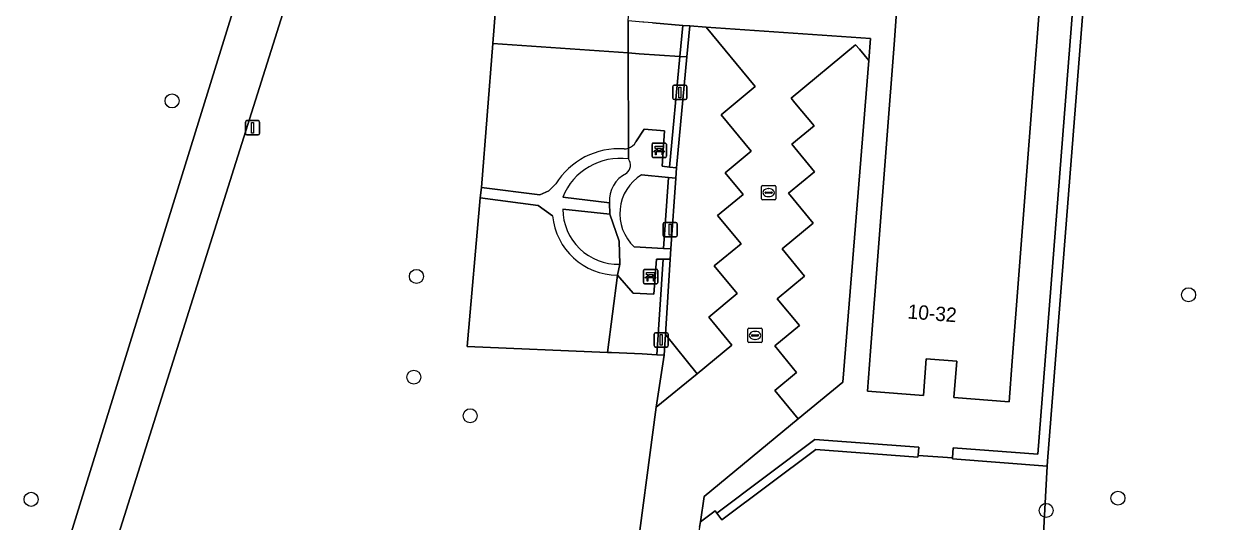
# Model space of a CAD drawing. Extents: x 161402 to 161933, y 381647 to 382315.
# Drawn here: x 161588.1 to 161672, y 381714.1 to 381748.8 of the extents above; entities that cross this region are included whole.
import ezdxf

# ---------------------------------------------------------------- set-up
doc = ezdxf.new("R2010")
doc.units = 0
for name, color, linetype in [('IMGEO_Bank', 7, 'Continuous'), ('IMGEO_Boom', 7, 'Continuous'), ('IMGEO_Groenvoorziening', 7, 'Continuous'), ('IMGEO_Haag', 7, 'Continuous'), ('IMGEO_Hek', 7, 'Continuous'), ('IMGEO_Kolk', 7, 'Continuous'), ('IMGEO_Lichtmast', 7, 'Continuous'), ('IMGEO_Pand', 7, 'Continuous'), ('IMGEO_Pand_nummerreeks', 7, 'Continuous'), ('IMGEO_Parkeervlak_open', 7, 'Continuous'), ('IMGEO_Rijbaan_lokaal_open', 7, 'Continuous'), ('IMGEO_Voetpad_gesloten', 7, 'Continuous'), ('IMGEO_Voetpad_open', 7, 'Continuous')]:
    doc.layers.add(name, color=color, linetype=linetype)

msp = doc.modelspace()

# ---------------------------------------------------------------- linework, layer by layer
at = {"layer": 'IMGEO_Bank'}
for p, q in [((161631.866, 381739.608), (161631.866, 381740.449)), ((161631.866, 381740.449), (161631.866, 381739.608)), ((161631.941, 381740.533), (161632.782, 381740.533)), ((161632.782, 381740.533), (161631.941, 381740.533)), ((161632.563, 381739.931), (161632.17, 381739.931)), ((161632.175, 381740.039), (161632.175, 381740.145)), ((161632.219, 381740.145), (161632.219, 381740.039)), ((161632.507, 381740.151), (161632.225, 381740.151)), ((161632.225, 381740.033), (161632.507, 381740.033)), ((161632.513, 381740.039), (161632.513, 381740.145)), ((161632.557, 381740.145), (161632.557, 381740.039)), ((161632.866, 381740.458), (161632.866, 381739.617)), ((161632.866, 381739.617), (161632.866, 381740.458)), ((161632.791, 381739.533), (161631.95, 381739.533)), ((161631.95, 381739.533), (161632.791, 381739.533)), ((161631.268, 381730.81), (161631.268, 381731.651)), ((161631.268, 381731.651), (161631.268, 381730.81)), ((161631.343, 381731.735), (161632.184, 381731.735)), ((161632.184, 381731.735), (161631.343, 381731.735)), ((161632.268, 381731.66), (161632.268, 381730.819)), ((161632.268, 381730.819), (161632.268, 381731.66)), ((161632.193, 381730.735), (161631.352, 381730.735)), ((161631.352, 381730.735), (161632.193, 381730.735)), ((161631.965, 381731.133), (161631.572, 381731.133)), ((161631.577, 381731.241), (161631.577, 381731.347)), ((161631.621, 381731.347), (161631.621, 381731.241)), ((161631.909, 381731.353), (161631.627, 381731.353)), ((161631.627, 381731.235), (161631.909, 381731.235)), ((161631.915, 381731.241), (161631.915, 381731.347)), ((161631.959, 381731.347), (161631.959, 381731.241))]:
    msp.add_line(p, q, dxfattribs=at)
for points in [[(161632.113, 381739.931), (161631.971, 381739.931), (161632.083, 381740.033), (161632.169, 381740.033)], [(161632.169, 381740.151), (161632.083, 381740.151), (161632.083, 381740.312), (161632.646, 381740.312), (161632.646, 381740.151), (161632.563, 381740.151)], [(161632.163, 381739.924), (161632.163, 381739.717), (161632.12, 381739.717), (161632.12, 381739.924)], [(161632.563, 381740.033), (161632.646, 381740.033), (161632.758, 381739.931), (161632.619, 381739.931)], [(161632.613, 381739.924), (161632.613, 381739.717), (161632.569, 381739.717), (161632.569, 381739.924)], [(161631.515, 381731.133), (161631.373, 381731.133), (161631.485, 381731.235), (161631.571, 381731.235)], [(161631.571, 381731.353), (161631.485, 381731.353), (161631.485, 381731.514), (161632.048, 381731.514), (161632.048, 381731.353), (161631.965, 381731.353)], [(161631.565, 381731.126), (161631.565, 381730.919), (161631.522, 381730.919), (161631.522, 381731.126)], [(161631.965, 381731.235), (161632.048, 381731.235), (161632.16, 381731.133), (161632.021, 381731.133)], [(161632.015, 381731.126), (161632.015, 381730.919), (161631.971, 381730.919), (161631.971, 381731.126)]]:
    msp.add_lwpolyline(points, dxfattribs=at)
for centre, radius, start, end in [((161631.944, 381740.455), 0.0779, 92.4484, 184.28452), ((161631.944, 381740.455), 0.0779, 92.4484, 184.28452), ((161632.113, 381739.924), 0.00671, 2.89567, 87.10433), ((161632.17, 381739.924), 0.00671, 92.89567, 177.10433), ((161632.168, 381740.144), 0.00671, 2.89567, 87.10433), ((161632.168, 381740.04), 0.00671, 272.89567, 357.10433), ((161632.225, 381740.144), 0.00671, 92.89567, 177.10433), ((161632.225, 381740.04), 0.00671, 182.89567, 267.10433), ((161632.507, 381740.144), 0.00671, 2.89567, 87.10433), ((161632.507, 381740.04), 0.00671, 272.89567, 357.10433), ((161632.564, 381740.144), 0.00671, 92.89567, 177.10433), ((161632.564, 381740.04), 0.00671, 182.89567, 267.10433), ((161632.562, 381739.924), 0.00671, 2.89567, 87.10433), ((161632.619, 381739.924), 0.00671, 92.89567, 177.10433), ((161632.788, 381740.455), 0.0779, 2.4484, 94.28452), ((161632.788, 381740.455), 0.0779, 2.4484, 94.28452), ((161631.944, 381739.611), 0.0779, 182.4484, 274.28452), ((161631.944, 381739.611), 0.0779, 182.4484, 274.28452), ((161632.788, 381739.611), 0.0779, 272.4484, 4.28452), ((161632.788, 381739.611), 0.0779, 272.4484, 4.28452), ((161631.346, 381731.657), 0.0779, 92.4484, 184.28452), ((161631.346, 381731.657), 0.0779, 92.4484, 184.28452), ((161632.19, 381731.657), 0.0779, 2.4484, 94.28452), ((161632.19, 381731.657), 0.0779, 2.4484, 94.28452), ((161631.346, 381730.813), 0.0779, 182.4484, 274.28452), ((161631.346, 381730.813), 0.0779, 182.4484, 274.28452), ((161631.515, 381731.126), 0.00671, 2.89567, 87.10433), ((161631.572, 381731.126), 0.00671, 92.89567, 177.10433), ((161631.57, 381731.346), 0.00671, 2.89567, 87.10433), ((161631.57, 381731.242), 0.00671, 272.89567, 357.10433), ((161631.627, 381731.346), 0.00671, 92.89567, 177.10433), ((161631.627, 381731.242), 0.00671, 182.89567, 267.10433), ((161631.909, 381731.346), 0.00671, 2.89567, 87.10433), ((161631.909, 381731.242), 0.00671, 272.89567, 357.10433), ((161631.966, 381731.346), 0.00671, 92.89567, 177.10433), ((161631.966, 381731.242), 0.00671, 182.89567, 267.10433), ((161631.964, 381731.126), 0.00671, 2.89567, 87.10433), ((161632.021, 381731.126), 0.00671, 92.89567, 177.10433), ((161632.19, 381730.813), 0.0779, 272.4484, 4.28452), ((161632.19, 381730.813), 0.0779, 272.4484, 4.28452)]:
    msp.add_arc(centre, radius, start, end, dxfattribs=at)
at = {"layer": 'IMGEO_Boom'}
for centre in [(161598.377, 381743.475), (161615.428, 381731.244), (161669.305, 381729.962), (161615.249, 381724.221), (161619.18, 381721.53), (161588.542, 381715.703), (161664.377, 381715.786), (161659.366, 381714.93)]:
    msp.add_circle(centre, 0.489, dxfattribs=at)
at = {"layer": 'IMGEO_Groenvoorziening'}
for points in [[(161588.768, 381710.585), (161590.391, 381710.295), (161602.713, 381750), (161618.166, 381798.995)], [(161663.284, 381767.646), (161664.69, 381767.597), (161668.364, 381767.469), (161668.237, 381759.952), (161664.228, 381760.017), (161662.713, 381760.042), (161661.941, 381749.945), (161659.461, 381718.372), (161659.442, 381718.025), (161658.506, 381700.881), (161673.928, 381698.758), (161680.023, 381713.112), (161687.661, 381714.218), (161685.628, 381737.233), (161688.746, 381737.387), (161691.747, 381737.535), (161690.482, 381750)], [(161629.207, 381767.096), (161621.922, 381762.295), (161620.756, 381747.469), (161630.207, 381746.819), (161630.203, 381749.059), (161630.276, 381750), (161630.835, 381757.212), (161630.915, 381761.438), (161639.403, 381761.221), (161639.486, 381762.057), (161638.004, 381762.183), (161634.216, 381762.507)], [(161606.251, 381750), (161593.549, 381709.799), (161595.559, 381709.521), (161607.044, 381707.963), (161607.264, 381709.577), (161610.846, 381709.061), (161610.603, 381707.437), (161625.819, 381705.367), (161626.558, 381710.972), (161626.855, 381710.928), (161630.603, 381710.376), (161632.151, 381722.118), (161632.708, 381725.764), (161632.208, 381725.787), (161631.169, 381725.836), (161629.04, 381725.928), (161628.771, 381725.94), (161618.968, 381726.363), (161619.878, 381736.709), (161619.968, 381737.446), (161620.756, 381747.469), (161621.922, 381762.295)], [(161630.218, 381740.179), (161630.207, 381746.819), (161620.756, 381747.469), (161619.968, 381737.446), (161624.039, 381736.932), (161624.661, 381737.206), (161625.145, 381737.685)], [(161630.731, 381740.617), (161631.321, 381741.506), (161632.748, 381741.385), (161632.564, 381738.922), (161633.077, 381738.869), (161633.805, 381746.571), (161630.967, 381746.766), (161630.207, 381746.819), (161630.218, 381740.179)], [(161630.617, 381733.304), (161632.678, 381733.185), (161633.026, 381738.144), (161631.134, 381738.322)], [(161624.931, 381735.468), (161623.917, 381736.185), (161619.878, 381736.709), (161618.968, 381726.363), (161628.771, 381725.94), (161629.458, 381731.326)], [(161625.635, 381736.767), (161628.902, 381736.38)], [(161629.611, 381732.088), (161629.564, 381733.696), (161628.935, 381735.57), (161625.64, 381735.928)]]:
    msp.add_lwpolyline(points, dxfattribs=at)
for points in [[(161662.713, 381760.042), (161662.409, 381760.047), (161662.012, 381760.054), (161661.227, 381750), (161658.796, 381718.845), (161652.885, 381719.282), (161652.831, 381718.594), (161652.825, 381718.515), (161659.442, 381718.025), (161659.461, 381718.372), (161661.941, 381749.945)], [(161634.01, 381748.744), (161631.893, 381748.919), (161631.295, 381748.969), (161631.218, 381748.975), (161630.203, 381749.059), (161630.207, 381746.819), (161630.967, 381746.766), (161633.805, 381746.571)], [(161634.304, 381746.537), (161634.509, 381748.703), (161634.01, 381748.744), (161633.805, 381746.571)], [(161633.575, 381738.817), (161634.304, 381746.537), (161633.805, 381746.571), (161633.077, 381738.869)], [(161633.177, 381733.156), (161633.524, 381738.097), (161633.026, 381738.144), (161632.678, 381733.185)], [(161629.04, 381725.928), (161631.169, 381725.836), (161632.208, 381725.787), (161632.641, 381732.452), (161632.191, 381732.454), (161631.991, 381729.995), (161630.552, 381730.063), (161629.458, 381731.326), (161628.771, 381725.94)], [(161633.142, 381732.449), (161632.641, 381732.452), (161632.208, 381725.787), (161632.708, 381725.764), (161632.8, 381727.185)], [(161643.225, 381719.866), (161636.381, 381714.742), (161636.738, 381714.264), (161643.3, 381719.172), (161650.424, 381718.643), (161650.433, 381718.759), (161650.477, 381719.329)], [(161659.442, 381718.025), (161652.825, 381718.515), (161652.831, 381718.594), (161650.433, 381718.759), (161650.424, 381718.643), (161643.3, 381719.172), (161636.738, 381714.264), (161636.381, 381714.742), (161636.265, 381714.897), (161635.242, 381714.132), (161635.188, 381713.771), (161633.775, 381704.284), (161633.894, 381704.268), (161658.506, 381700.881)]]:
    msp.add_lwpolyline(points, close=True, dxfattribs=at)
for centre, radius, start, end in [((161629.553, 381734.955), 5.185, 86.02348, 148.23538), ((161629.912, 381741.073), 0.945, 270.07116, 288.9144), ((161629.92, 381741.047), 0.918, 288.93213, 332.04935), ((161629.644, 381735.151), 4.322, 82.35266, 158.04824), ((161629.626, 381739.001), 0.735, 308.0568, 36.20596), ((161631.014, 381736.523), 2.117, 116.20928, 183.87279), ((161632.793, 381735.615), 3.174, 121.49947, 226.73578), ((161629.508, 381735.954), 3.868, 180.39129, 271.53037), ((161629.486, 381735.902), 4.576, 185.4366, 269.64919)]:
    msp.add_arc(centre, radius, start, end, dxfattribs=at)
at = {"layer": 'IMGEO_Haag'}
for points in [[(161662.713, 381760.042), (161662.409, 381760.047), (161662.012, 381760.054), (161661.227, 381750), (161658.796, 381718.845), (161652.885, 381719.282), (161652.831, 381718.594), (161652.825, 381718.515), (161659.442, 381718.025), (161659.461, 381718.372), (161661.941, 381749.945)], [(161634.509, 381748.703), (161634.01, 381748.744), (161633.805, 381746.571), (161634.304, 381746.537)], [(161634.304, 381746.537), (161633.805, 381746.571), (161633.077, 381738.869), (161633.575, 381738.817)], [(161633.177, 381733.156), (161633.524, 381738.097), (161633.026, 381738.144), (161632.678, 381733.185)], [(161633.142, 381732.449), (161632.641, 381732.452), (161632.208, 381725.787), (161632.708, 381725.764), (161632.8, 381727.185)], [(161643.225, 381719.866), (161636.381, 381714.742), (161636.738, 381714.264), (161643.3, 381719.172), (161650.424, 381718.643), (161650.433, 381718.759), (161650.477, 381719.329)]]:
    msp.add_lwpolyline(points, close=True, dxfattribs=at)
at = {"layer": 'IMGEO_Hek'}
for points in [[(161630.207, 381746.819), (161620.756, 381747.469)], [(161630.967, 381746.766), (161630.207, 381746.819)], [(161633.805, 381746.571), (161630.967, 381746.766)], [(161634.304, 381746.537), (161633.805, 381746.571)]]:
    msp.add_lwpolyline(points, dxfattribs=at)
at = {"layer": 'IMGEO_Kolk'}
for p, q in [((161639.503, 381736.655), (161639.503, 381737.507)), ((161639.578, 381737.581), (161640.43, 381737.581)), ((161640.504, 381737.507), (161640.504, 381736.655)), ((161640.43, 381736.581), (161639.578, 381736.581)), ((161639.762, 381737.075), (161639.762, 381737.087)), ((161640.2, 381737.038), (161639.802, 381737.038)), ((161639.805, 381737.124), (161640.203, 381737.124)), ((161640.014, 381736.801), (161639.989, 381736.801)), ((161639.991, 381737.361), (161640.016, 381737.361)), ((161640.246, 381737.087), (161640.246, 381737.075)), ((161638.556, 381726.702), (161638.556, 381727.554)), ((161638.631, 381727.628), (161639.483, 381727.628)), ((161639.044, 381727.408), (161639.069, 381727.408)), ((161639.557, 381727.554), (161639.557, 381726.702)), ((161639.483, 381726.628), (161638.631, 381726.628)), ((161638.815, 381727.122), (161638.815, 381727.134)), ((161639.253, 381727.085), (161638.855, 381727.085)), ((161638.858, 381727.171), (161639.256, 381727.171)), ((161639.067, 381726.848), (161639.042, 381726.848)), ((161639.299, 381727.134), (161639.299, 381727.122))]:
    msp.add_line(p, q, dxfattribs=at)
for points in [[(161639.503, 381736.655), (161639.503, 381737.507)], [(161639.578, 381737.581), (161640.43, 381737.581)], [(161640.504, 381737.507), (161640.504, 381736.655)], [(161640.43, 381736.581), (161639.578, 381736.581)], [(161638.556, 381726.702), (161638.556, 381727.554)], [(161638.631, 381727.628), (161639.483, 381727.628)], [(161639.557, 381727.554), (161639.557, 381726.702)], [(161639.483, 381726.628), (161638.631, 381726.628)]]:
    msp.add_lwpolyline(points, dxfattribs=at)
for centre, radius, start, end in [((161639.58, 381737.505), 0.0765, 91.55205, 178.44795), ((161639.58, 381737.505), 0.0765, 91.55205, 178.44795), ((161640.428, 381737.505), 0.0765, 1.55205, 88.44795), ((161640.428, 381737.505), 0.0765, 1.55205, 88.44795), ((161639.58, 381736.657), 0.0765, 181.55205, 268.44795), ((161639.58, 381736.657), 0.0765, 181.55205, 268.44795), ((161639.802, 381737.084), 0.0403, 85.87752, 175.75265), ((161639.799, 381737.074), 0.0366, 178.93798, 274.71019), ((161640.203, 381737.081), 0.043, 264.86636, 352.45326), ((161640.207, 381737.086), 0.0386, 1.73085, 96.63898), ((161640.428, 381736.657), 0.0765, 271.55205, 358.44795), ((161640.428, 381736.657), 0.0765, 271.55205, 358.44795), ((161638.633, 381727.552), 0.0765, 91.55205, 178.44795), ((161638.633, 381727.552), 0.0765, 91.55205, 178.44795), ((161639.481, 381727.552), 0.0765, 1.55205, 88.44795), ((161639.481, 381727.552), 0.0765, 1.55205, 88.44795), ((161638.633, 381726.704), 0.0765, 181.55205, 268.44795), ((161638.633, 381726.704), 0.0765, 181.55205, 268.44795), ((161638.855, 381727.131), 0.0403, 85.87752, 175.75265), ((161638.852, 381727.121), 0.0366, 178.93798, 274.71019), ((161639.256, 381727.128), 0.043, 264.86636, 352.45326), ((161639.26, 381727.133), 0.0386, 1.73085, 96.63898), ((161639.481, 381726.704), 0.0765, 271.55205, 358.44795), ((161639.481, 381726.704), 0.0765, 271.55205, 358.44795)]:
    msp.add_arc(centre, radius, start, end, dxfattribs=at)
for centre, major_axis, ratio, start_param, end_param in [((161639.99, 381737.081), (-0.387, 0.002), 0.722429, 4.712389, 7.853982), ((161640.015, 381737.081), (-0.39, 0.002), 0.717154, 1.570796, 4.712389), ((161639.043, 381727.128), (-0.387, 0.002), 0.722429, 4.712389, 7.853982), ((161639.068, 381727.128), (-0.39, 0.002), 0.717154, 1.570796, 4.712389)]:
    msp.add_ellipse(centre, major_axis=major_axis, ratio=ratio, start_param=start_param, end_param=end_param, dxfattribs=at)
at = {"layer": 'IMGEO_Lichtmast'}
for p, q in [((161633.316, 381743.669), (161633.316, 381744.469)), ((161633.316, 381744.469), (161633.316, 381743.669)), ((161633.416, 381744.569), (161634.206, 381744.569)), ((161634.206, 381744.569), (161633.416, 381744.569)), ((161634.306, 381744.469), (161634.306, 381743.669)), ((161634.306, 381743.669), (161634.306, 381744.469)), ((161634.206, 381743.569), (161633.416, 381743.569)), ((161633.416, 381743.569), (161634.206, 381743.569)), ((161603.501, 381741.203), (161603.501, 381742.003)), ((161603.501, 381742.003), (161603.501, 381741.203)), ((161603.601, 381742.103), (161604.391, 381742.103)), ((161604.391, 381742.103), (161603.601, 381742.103)), ((161604.491, 381742.003), (161604.491, 381741.203)), ((161604.491, 381741.203), (161604.491, 381742.003)), ((161604.391, 381741.103), (161603.601, 381741.103)), ((161603.601, 381741.103), (161604.391, 381741.103)), ((161632.637, 381734.099), (161632.637, 381734.899)), ((161632.637, 381734.899), (161632.637, 381734.099)), ((161632.737, 381734.999), (161633.527, 381734.999)), ((161633.527, 381734.999), (161632.737, 381734.999)), ((161633.627, 381734.899), (161633.627, 381734.099)), ((161633.627, 381734.099), (161633.627, 381734.899)), ((161633.527, 381733.999), (161632.737, 381733.999)), ((161632.737, 381733.999), (161633.527, 381733.999)), ((161632.006, 381726.416), (161632.006, 381727.216)), ((161632.006, 381727.216), (161632.006, 381726.416)), ((161632.106, 381727.316), (161632.896, 381727.316)), ((161632.896, 381727.316), (161632.106, 381727.316)), ((161632.996, 381727.216), (161632.996, 381726.416)), ((161632.996, 381726.416), (161632.996, 381727.216)), ((161632.896, 381726.316), (161632.106, 381726.316)), ((161632.106, 381726.316), (161632.896, 381726.316))]:
    msp.add_line(p, q, dxfattribs=at)
for points in [[(161633.736, 381744.444), (161633.886, 381744.444), (161633.886, 381743.694), (161633.736, 381743.694), (161633.736, 381744.444)], [(161603.921, 381741.978), (161604.071, 381741.978), (161604.071, 381741.228), (161603.921, 381741.228), (161603.921, 381741.978)], [(161633.057, 381734.874), (161633.207, 381734.874), (161633.207, 381734.124), (161633.057, 381734.124), (161633.057, 381734.874)], [(161632.426, 381727.191), (161632.576, 381727.191), (161632.576, 381726.441), (161632.426, 381726.441), (161632.426, 381727.191)]]:
    msp.add_lwpolyline(points, dxfattribs=at)
for centre, start, end in [((161633.416, 381744.469), 90, 180), ((161633.416, 381744.469), 90, 180), ((161634.206, 381744.469), 0, 90), ((161634.206, 381744.469), 360, 90), ((161633.416, 381743.669), 180, 270), ((161633.416, 381743.669), 180, 270), ((161634.206, 381743.669), 270, 0), ((161634.206, 381743.669), 270, 0), ((161603.601, 381742.003), 90, 180), ((161603.601, 381742.003), 90, 180), ((161604.391, 381742.003), 0, 90), ((161604.391, 381742.003), 360, 90), ((161603.601, 381741.203), 180, 270), ((161603.601, 381741.203), 180, 270), ((161604.391, 381741.203), 270, 0), ((161604.391, 381741.203), 270, 0), ((161632.737, 381734.899), 90, 180), ((161632.737, 381734.899), 90, 180), ((161633.527, 381734.899), 0, 90), ((161633.527, 381734.899), 360, 90), ((161632.737, 381734.099), 180, 270), ((161632.737, 381734.099), 180, 270), ((161633.527, 381734.099), 270, 0), ((161633.527, 381734.099), 270, 0), ((161632.106, 381727.216), 90, 180), ((161632.106, 381727.216), 90, 180), ((161632.896, 381727.216), 0, 90), ((161632.896, 381727.216), 360, 90), ((161632.106, 381726.416), 180, 270), ((161632.106, 381726.416), 180, 270), ((161632.896, 381726.416), 270, 0), ((161632.896, 381726.416), 270, 0)]:
    msp.add_arc(centre, 0.1, start, end, dxfattribs=at)
at = {"layer": 'IMGEO_Pand'}
msp.add_lwpolyline([(161648.953, 381750), (161648.778, 381747.713), (161647.117, 381726.028), (161646.904, 381723.247), (161650.799, 381722.944), (161650.997, 381725.499), (161653.123, 381725.334), (161652.926, 381722.793), (161656.794, 381722.493), (161657.001, 381725.343), (161658.913, 381750)], dxfattribs=at)
at = {"layer": 'IMGEO_Parkeervlak_open'}
for points in [[(161636.689, 381742.513), (161639.068, 381744.479), (161635.642, 381748.624), (161634.509, 381748.703), (161634.304, 381746.537), (161633.575, 381738.817), (161633.524, 381738.097), (161633.177, 381733.156), (161633.142, 381732.449), (161632.8, 381727.185), (161635.02, 381724.462), (161637.435, 381726.458), (161635.824, 381728.407), (161637.8, 381730.041), (161636.204, 381731.973), (161638.077, 381733.521), (161636.443, 381735.498), (161638.216, 381736.962), (161636.972, 381738.467), (161638.791, 381739.97)], [(161646.983, 381746.288), (161646.334, 381747.073), (161646.07, 381747.393), (161641.565, 381743.67), (161641.829, 381743.351), (161643.169, 381741.729), (161641.627, 381740.455), (161643.209, 381738.541), (161641.388, 381737.037), (161643.114, 381734.948), (161640.946, 381733.156), (161642.512, 381731.261), (161640.607, 381729.687), (161642.15, 381727.821), (161640.427, 381726.397), (161641.957, 381724.546), (161640.427, 381723.282), (161642.06, 381721.305), (161645.186, 381723.878)]]:
    msp.add_lwpolyline(points, close=True, dxfattribs=at)
at = {"layer": 'IMGEO_Rijbaan_lokaal_open'}
msp.add_lwpolyline([(161635.188, 381713.771), (161635.242, 381714.132), (161635.507, 381715.911), (161642.06, 381721.305), (161640.427, 381723.282), (161641.957, 381724.546), (161640.427, 381726.397), (161642.15, 381727.821), (161640.607, 381729.687), (161642.512, 381731.261), (161640.946, 381733.156), (161643.114, 381734.948), (161641.388, 381737.037), (161643.209, 381738.541), (161641.627, 381740.455), (161643.169, 381741.729), (161641.829, 381743.351), (161641.565, 381743.67), (161646.07, 381747.393), (161646.334, 381747.073), (161646.983, 381746.288), (161647.106, 381747.829), (161635.642, 381748.624), (161639.068, 381744.479), (161636.689, 381742.513), (161638.791, 381739.97), (161636.972, 381738.467), (161638.216, 381736.962), (161636.443, 381735.498), (161638.077, 381733.521), (161636.204, 381731.973), (161637.8, 381730.041), (161635.824, 381728.407), (161637.435, 381726.458), (161635.02, 381724.462), (161632.151, 381722.118), (161630.603, 381710.376)], dxfattribs=at)
at = {"layer": 'IMGEO_Voetpad_gesloten'}
msp.add_lwpolyline([(161619.472, 381803.135), (161618.166, 381798.995), (161602.713, 381750), (161590.391, 381710.295), (161591.839, 381710.036), (161593.549, 381709.799), (161606.251, 381750), (161622.439, 381801.233), (161623.084, 381803.274), (161623.636, 381805.021), (161676.505, 381798.883), (161677.707, 381798.743), (161684.945, 381797.903), (161689.601, 381798.897), (161694.963, 381800.536), (161716.413, 381806.426), (161720.944, 381807.67), (161724.1, 381808.537)], dxfattribs=at)
at = {"layer": 'IMGEO_Voetpad_open'}
for points in [[(161631.893, 381748.919), (161634.01, 381748.744), (161634.509, 381748.703), (161635.642, 381748.624), (161647.106, 381747.829), (161646.983, 381746.288), (161645.186, 381723.878), (161642.06, 381721.305), (161635.507, 381715.911), (161635.242, 381714.132), (161636.265, 381714.897), (161636.381, 381714.742), (161643.225, 381719.866), (161650.477, 381719.329), (161650.433, 381718.759), (161652.831, 381718.594), (161652.885, 381719.282), (161658.796, 381718.845), (161661.227, 381750)], [(161658.913, 381750), (161657.001, 381725.343), (161656.794, 381722.493), (161652.926, 381722.793), (161653.123, 381725.334), (161650.997, 381725.499), (161650.799, 381722.944), (161646.904, 381723.247), (161647.117, 381726.028), (161648.778, 381747.713), (161648.953, 381750)], [(161631.134, 381738.322), (161633.026, 381738.144), (161633.524, 381738.097), (161633.575, 381738.817), (161633.077, 381738.869), (161632.564, 381738.922), (161632.748, 381741.385), (161631.321, 381741.506), (161630.731, 381740.617)], [(161630.218, 381740.179), (161630.219, 381739.435)], [(161630.219, 381739.435), (161630.218, 381740.179)], [(161625.145, 381737.685), (161624.661, 381737.206), (161624.039, 381736.932), (161619.968, 381737.446), (161619.878, 381736.709), (161623.917, 381736.185), (161624.931, 381735.468)], [(161625.64, 381735.928), (161628.935, 381735.57), (161628.902, 381736.38), (161625.635, 381736.767)], [(161628.902, 381736.38), (161628.935, 381735.57), (161629.564, 381733.696), (161629.611, 381732.088), (161629.458, 381731.326), (161630.552, 381730.063), (161631.991, 381729.995), (161632.191, 381732.454), (161632.641, 381732.452), (161633.142, 381732.449), (161633.177, 381733.156), (161632.678, 381733.185), (161630.617, 381733.304)], [(161629.458, 381731.326), (161629.611, 381732.088)]]:
    msp.add_lwpolyline(points, dxfattribs=at)
msp.add_lwpolyline([(161632.8, 381727.185), (161632.708, 381725.764), (161632.151, 381722.118), (161635.02, 381724.462)], close=True, dxfattribs=at)
for centre, radius, start, end in [((161629.553, 381734.955), 5.185, 86.02348, 148.23538), ((161629.912, 381741.073), 0.945, 270.07116, 288.9144), ((161629.92, 381741.047), 0.918, 288.93213, 332.04935), ((161629.644, 381735.151), 4.322, 82.35266, 158.04824), ((161629.626, 381739.001), 0.735, 308.0568, 36.20596), ((161631.014, 381736.523), 2.117, 116.20928, 183.87279), ((161632.793, 381735.615), 3.174, 121.49947, 226.73578), ((161629.508, 381735.954), 3.868, 180.39129, 271.53037), ((161629.486, 381735.902), 4.576, 185.4366, 269.64919)]:
    msp.add_arc(centre, radius, start, end, dxfattribs=at)

# ---------------------------------------------------------------- texts
at = {"layer": 'IMGEO_Pand_nummerreeks'}
msp.add_text('10-32', height=1, rotation=355.55958, dxfattribs=at).set_placement((161649.67, 381728.31))

doc.saveas('drawing.dxf')
